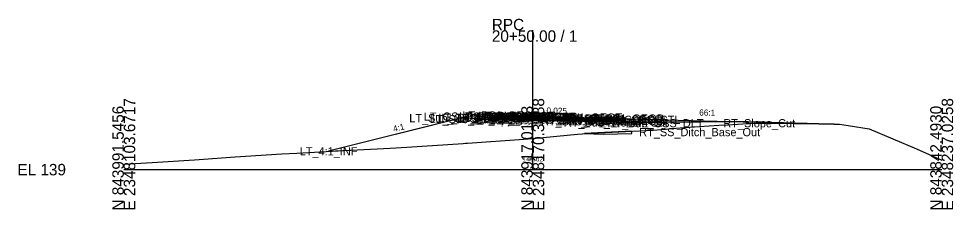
# Model space of a CAD drawing. Extents: x -26 to 203, y -10 to 7538.
# Drawn here: x -25.7 to 202.8, y 6990.3 to 7036.9 of the extents above; entities that cross this region are included whole.
import ezdxf

# ---------------------------------------------------------------- set-up
doc = ezdxf.new("R2010")
doc.units = 0
for name, color, linetype in [('Default', 7, 'Continuous'), ('Exist Cross Section Cell', 7, 'Continuous'), ('Exist XS Center Line Elevation Label', 7, 'Continuous'), ('Exist XS Ground Line', 7, 'Continuous'), ('Prop CMT Pvmt Course 1', 7, 'Continuous'), ('Prop CMT Pvmt Course 2', 7, 'Continuous'), ('Prop CMT Pvmt Course 3', 7, 'Continuous'), ('Prop CMT Pvmt Surface', 7, 'Continuous'), ('Prop CMT Pvmt Surface Shoulder', 7, 'Continuous'), ('Prop CMT Shld Paved Course 1', 7, 'Continuous'), ('Prop CMT Shld Paved Course 2', 7, 'Continuous'), ('Prop CMT Shld Paved Course 3', 7, 'Continuous'), ('Prop CMT Slope Grass', 7, 'Continuous'), ('Prop CMT Subgrade Earthwork', 7, 'Continuous'), ('Prop Road Sect_ Recs - UC (Outline)', 7, 'Continuous'), ('Prop XS Earthwork Shape', 7, 'Continuous'), ('Prop XS SE Text', 7, 'Continuous'), ('Prop XS Side Slope Text', 7, 'Continuous'), ('Scratch_Level_0', 7, 'Continuous')]:
    doc.layers.add(name, color=color, linetype=linetype)

msp = doc.modelspace()

# ---------------------------------------------------------------- linework, layer by layer
at = {"layer": 'Exist Cross Section Cell'}
for p, q in [((100, 7000), (100, 7034.05)), ((0, 7000), (100, 7000)), ((100, 7000), (200, 7000))]:
    msp.add_line(p, q, dxfattribs=at)
at = {"layer": 'Exist XS Ground Line'}
msp.add_lwpolyline([(0, 7001.36), (6.96, 7001.78), (17.28, 7002.41), (27.2, 7003.09), (38.63, 7003.85), (42.29, 7004.06), (55.24, 7004.77), (55.55, 7004.8), (65.16, 7005.27), (69.21, 7005.47), (83.01, 7006.41), (83.55, 7006.48), (84.05, 7006.49), (97.86, 7007.41), (100, 7007.62), (110.94, 7008.7), (114.42, 7008.92), (122.65, 7009.29), (129.41, 7009.68), (136.07, 7010.19), (145.49, 7010.84), (147.69, 7010.98), (150.03, 7011.12), (151.37, 7011.2), (152.19, 7011.26), (152.86, 7011.29), (154.78, 7011.34), (155.41, 7011.35), (156.29, 7011.35), (157.6, 7011.35), (158.82, 7011.34), (159.41, 7011.34), (160.06, 7011.34), (162.18, 7011.33), (162.94, 7011.32), (163.8, 7011.31), (164.73, 7011.3), (165.54, 7011.29), (167.53, 7011.27), (168.85, 7011.25), (170.37, 7011.23), (171.24, 7011.21), (171.61, 7011.2), (172.21, 7011.19), (173.67, 7011.14), (174.54, 7011.09), (175.04, 7011.1), (177.16, 7010.8), (182.23, 7009.97), (193.86, 7005.07), (200, 7002.28)], dxfattribs=at)
at = {"layer": 'Prop CMT Pvmt Course 1'}
for p, q in [((100, 7013.04), (96, 7013.14)), ((96, 7013.14), (96, 7012.89)), ((96, 7012.89), (100, 7012.79)), ((100, 7012.79), (100, 7013.04)), ((100, 7013.04), (112, 7012.74)), ((100, 7012.79), (100, 7013.04)), ((100, 7012.79), (100, 7012.92)), ((100, 7012.92), (100, 7012.92)), ((100, 7012.92), (100, 7012.79)), ((100, 7012.79), (100, 7012.92)), ((100, 7012.92), (100, 7012.92)), ((100, 7012.92), (100, 7012.79)), ((100, 7012.79), (100, 7012.79)), ((112, 7012.49), (100, 7012.79)), ((100, 7012.79), (100, 7012.79)), ((112, 7012.74), (112, 7012.49))]:
    msp.add_line(p, q, dxfattribs=at)
at = {"layer": 'Prop CMT Pvmt Course 2'}
for p, q in [((100, 7012.79), (96, 7012.89)), ((96, 7012.89), (96, 7012.56)), ((96, 7012.56), (100, 7012.46)), ((100, 7012.46), (100, 7012.79)), ((100, 7012.46), (100, 7012.79)), ((100, 7012.79), (112, 7012.49)), ((112, 7012.16), (100, 7012.46)), ((112, 7012.49), (112, 7012.16))]:
    msp.add_line(p, q, dxfattribs=at)
at = {"layer": 'Prop CMT Pvmt Course 3'}
for p, q in [((100, 7012.46), (96, 7012.56)), ((96, 7012.56), (96, 7012.23)), ((96, 7012.23), (100, 7012.13)), ((100, 7012.13), (100, 7012.46)), ((100, 7012.46), (112, 7012.16)), ((100, 7012.13), (100, 7012.46)), ((112, 7011.83), (100, 7012.13)), ((112, 7012.16), (112, 7011.83))]:
    msp.add_line(p, q, dxfattribs=at)
at = {"layer": 'Prop CMT Pvmt Surface'}
for q in [(96, 7013.14), (112, 7012.74)]:
    msp.add_line((100, 7013.04), q, dxfattribs=at)
at = {"layer": 'Prop CMT Pvmt Surface Shoulder'}
for p, q in [((96, 7013.14), (92, 7013.24)), ((112, 7012.74), (122, 7012.49))]:
    msp.add_line(p, q, dxfattribs=at)
at = {"layer": 'Prop CMT Shld Paved Course 1'}
for p, q in [((92, 7013.24), (91.76, 7013)), ((91.76, 7013), (96, 7012.89)), ((96, 7013.14), (92, 7013.24)), ((96, 7012.89), (96, 7013.14)), ((112, 7012.74), (122, 7012.49)), ((112, 7012.49), (112, 7012.74)), ((122.26, 7012.24), (112, 7012.49)), ((122, 7012.49), (122.26, 7012.24))]:
    msp.add_line(p, q, dxfattribs=at)
at = {"layer": 'Prop CMT Shld Paved Course 2'}
for p, q in [((91.76, 7013), (91.43, 7012.68)), ((91.43, 7012.68), (96, 7012.56)), ((96, 7012.89), (91.76, 7013)), ((96, 7012.56), (96, 7012.89)), ((112, 7012.49), (122.26, 7012.24)), ((112, 7012.16), (112, 7012.49)), ((122.6, 7011.9), (112, 7012.16)), ((122.26, 7012.24), (122.6, 7011.9))]:
    msp.add_line(p, q, dxfattribs=at)
at = {"layer": 'Prop CMT Shld Paved Course 3'}
for p, q in [((90.93, 7012.69), (90.61, 7012.36)), ((90.61, 7012.36), (96, 7012.23)), ((91.43, 7012.68), (90.93, 7012.69)), ((96, 7012.56), (91.43, 7012.68)), ((96, 7012.23), (96, 7012.56)), ((112, 7012.16), (122.6, 7011.9)), ((112, 7011.83), (112, 7012.16)), ((123.44, 7011.54), (112, 7011.83)), ((122.6, 7011.9), (123.1, 7011.88)), ((123.1, 7011.88), (123.44, 7011.54))]:
    msp.add_line(p, q, dxfattribs=at)
at = {"layer": 'Prop CMT Slope Grass'}
for p, q in [((84, 7012.96), (50.08, 7004.48)), ((92, 7013.24), (84, 7012.96)), ((122, 7012.49), (126, 7012.35)), ((126, 7012.35), (173.67, 7011.14))]:
    msp.add_line(p, q, dxfattribs=at)
at = {"layer": 'Prop CMT Subgrade Earthwork'}
for p, q in [((90.61, 7012.36), (82.41, 7012.57)), ((96, 7012.23), (90.61, 7012.36)), ((100, 7012.13), (96, 7012.23)), ((100, 7012.13), (112, 7011.83)), ((112, 7011.83), (123.44, 7011.54)), ((123.44, 7011.54), (149.84, 7011.75))]:
    msp.add_line(p, q, dxfattribs=at)
at = {"layer": 'Prop Road Sect_ Recs - UC (Outline)'}
msp.add_lwpolyline([(117.23, 7008.7), (124.2, 7008.8), (124.2, 7008.8), (124.19, 7009.39), (112.69, 7008.81)], close=True, dxfattribs=at)
at = {"layer": 'Prop XS Earthwork Shape'}
for points in [[(157.6, 7011.35), (158.82, 7011.34), (159.41, 7011.34), (160.06, 7011.34), (162.18, 7011.33), (162.94, 7011.32), (163.8, 7011.31), (164.73, 7011.3), (165.54, 7011.29), (167.53, 7011.27), (168.85, 7011.25), (169.99, 7011.23), (149.84, 7011.75), (123.44, 7011.54), (112, 7011.83), (100, 7012.13), (96, 7012.23), (90.61, 7012.36), (82.41, 7012.57), (50.08, 7004.48), (55.24, 7004.77), (55.55, 7004.8), (65.16, 7005.27), (69.21, 7005.47), (83.01, 7006.41), (83.55, 7006.48), (84.05, 7006.49), (97.86, 7007.41), (100, 7007.62), (110.94, 7008.7), (114.42, 7008.92), (122.65, 7009.29), (129.41, 7009.68), (136.07, 7010.19), (145.49, 7010.84), (147.69, 7010.98), (150.03, 7011.12), (151.37, 7011.2), (152.19, 7011.26), (152.86, 7011.29), (154.78, 7011.34), (155.41, 7011.35), (156.29, 7011.35)], [(170.37, 7011.23), (171.24, 7011.21), (171.61, 7011.2), (172.21, 7011.19), (173.67, 7011.14), (169.99, 7011.23)]]:
    msp.add_lwpolyline(points, close=True, dxfattribs=at)

# ---------------------------------------------------------------- texts
at = {"layer": 'Default'}
msp.add_text('-', height=0.0001, dxfattribs=at).set_placement((0, 7000))
at = {"layer": 'Exist Cross Section Cell'}
for s, p in [('RPC', (90, 7034.05)), ('20+50.00 / 1', (90, 7031.25)), ('EL 139', (-26, 6998.6))]:
    msp.add_text(s, height=2.8, dxfattribs=at).set_placement(p)
for s, p in [('E 2348103.6717', (2.8, 6990)), ('E 2348170.3488', (102.8, 6990)), ('E 2348237.0258', (202.8, 6990)), ('N 843991.5456', (0, 6990)), ('N 843917.0193', (100, 6990)), ('N 843842.4930', (200, 6990))]:
    msp.add_text(s, height=2.8, rotation=90, dxfattribs=at).set_placement(p)
at = {"layer": 'Exist XS Center Line Elevation Label'}
msp.add_text('146.62', height=1.2, dxfattribs=at).set_placement((97.5, 7002.02))
at = {"layer": 'Prop XS SE Text'}
msp.add_text('0.025', height=1.5, rotation=358.5679, dxfattribs=at).set_placement((103.34, 7013.71))
at = {"layer": 'Prop XS Side Slope Text'}
for s, rotation, p in [('66:1', 359.1319, (140.71, 7013.22)), ('4:1', 14.0362, (66.05, 7009.2))]:
    msp.add_text(s, height=1.5, rotation=rotation, dxfattribs=at).set_placement(p)
at = {"layer": 'Scratch_Level_0'}
for s, p in [('LT_Sub_OSS_DLT', (69.81, 7011.57)), ('LT_GS_OS_CTL', (73.37, 7011.96)), ('LT_PS3_Shelf_Out', (76.92, 7011.69)), ('LT_PS3_OEOP', (81.67, 7011.68)), ('LT_PS2_OEOP', (81.99, 7012)), ('LT_PS1_OEOP', (82.8, 7012.24)), ('LT_PV2_OEOT', (86.17, 7011.89)), ('LT_PV1_OEOT', (86.74, 7012.14)), ('RT_PV2_OEEOP', (89.26, 7011.79)), ('LT_PV2_OEEOP', (89.31, 7011.79)), ('RT_PV1_OEEOP', (89.83, 7011.92)), ('LT_PV1_OEEOP', (89.87, 7011.92)), ('RT_PV2_IEEOP', (89.91, 7011.79)), ('LT_PV2_IEEOP', (89.95, 7011.79)), ('RT_PV1_IEEOP', (90.47, 7011.92)), ('LT_PV1_IEEOP', (90.52, 7011.92)), ('PV2_PGL', (93.91, 7011.79)), ('PV1_PGL', (94.47, 7012.04)), ('RT_PV1_OEOT', (102.69, 7011.74)), ('LT_Sub_Trench_Out', (74.81, 7011.36)), ('LT_Sub_OEOT', (86.08, 7011.23)), ('LT_PV3_OEOT', (86.17, 7011.56)), ('RT_Sub_OEEOP', (89.17, 7011.13)), ('LT_Sub_OEEOP', (89.21, 7011.13)), ('RT_PV3_OEEOP', (89.26, 7011.46)), ('LT_PV3_OEEOP', (89.31, 7011.46)), ('RT_Sub_OEOT', (102.03, 7010.83)), ('RT_PV2_OEOT', (102.13, 7011.49)), ('RT_PV3_OEOT', (102.13, 7011.16)), ('RT_Sub_Trench_Out', (107.6, 7010.54)), ('RT_PS3_Shelf_Out', (109.04, 7010.88)), ('RT_PS2_OEOP', (112.45, 7011.24)), ('RT_PS1_OEOP', (112.76, 7011.49)), ('RT_PS3_OEOP', (112.79, 7010.9)), ('RT_GS_OS_CTL', (115.32, 7011.17)), ('RT_Sub_OSS_DLT', (118.27, 7010.35)), ('RT_Slope_Cut', (146.61, 7010.35)), ('RT_SS_Ditch_Base_Out', (126.03, 7008.17)), ('LT_4:1_INF', (43.01, 7003.48))]:
    msp.add_text(s, height=2, dxfattribs=at).set_placement(p)

doc.saveas('drawing.dxf')
